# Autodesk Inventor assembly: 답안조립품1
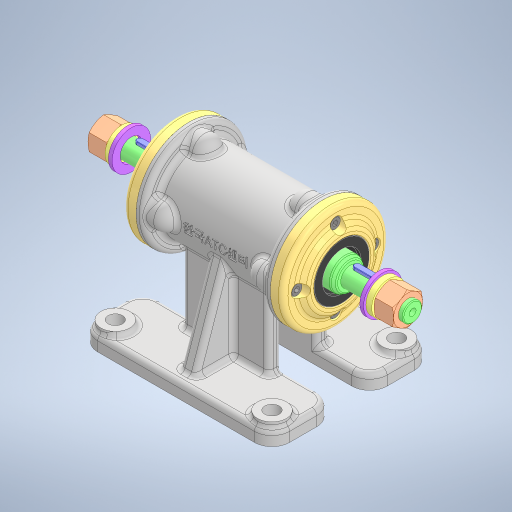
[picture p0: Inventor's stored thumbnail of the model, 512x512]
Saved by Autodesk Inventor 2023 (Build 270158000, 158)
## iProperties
Created: 2026-06
Part Number: 답안조립품1
Document SubType Name: Assembly
Designer: 4강의실
Author: 4강의실
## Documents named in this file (13)
- C:\Users\kimgi\Desktop\760603V1008\답안조립품1.iam
- C:\Users\kimgi\Desktop\760603V1008\본체.ipt
- C:\Users\kimgi\Desktop\760603V1008\6각 구멍붙이 볼트 M4x8.ipt
- C:\Users\kimgi\Desktop\760603V1008\6각 너트 M12x1.ipt
- C:\Users\kimgi\Desktop\760603V1008\V 벨트 풀리.ipt
- C:\Users\kimgi\Desktop\760603V1008\스퍼 기어.ipt
- C:\Users\kimgi\Desktop\760603V1008\스프링 와셔 M12.ipt
- C:\Users\kimgi\Desktop\760603V1008\오일 실 20 35 8.ipt
- C:\Users\kimgi\Desktop\760603V1008\축.ipt
- C:\Users\kimgi\Desktop\760603V1008\커버.ipt
- C:\Users\kimgi\Desktop\760603V1008\평 와셔 M12.ipt
- C:\Users\kimgi\Desktop\760603V1008\평행 키 4x4x14.ipt
- C:\Users\kimgi\Desktop\760603V1008\깊은 홈 볼 베어링 6904.ipt
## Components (11 placed, 3 different names)
1. 6각 너트 M12x1:1
2. V 벨트 풀리:1
3. 6각 너트 M12x1:2
4. 6각 구멍붙이 볼트 M4x8:2
5. 6각 구멍붙이 볼트 M4x8:3
6. 6각 구멍붙이 볼트 M4x8:4
7. 6각 구멍붙이 볼트 M4x8:5
8. 6각 구멍붙이 볼트 M4x8:1
9. 6각 구멍붙이 볼트 M4x8:6
10. 6각 구멍붙이 볼트 M4x8:7
11. 6각 구멍붙이 볼트 M4x8:8
